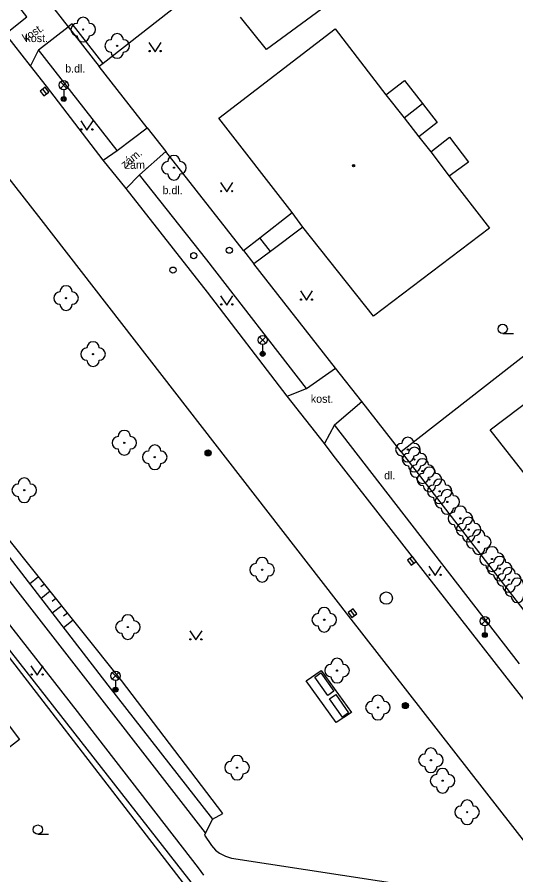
# Model space of a CAD drawing. Extents: x -600391 to -599491, y -1160176 to -1159402.
# Drawn here: x -600285.6 to -600245.1, y -1160073.3 to -1160003.6 of the extents above; entities that cross this region are included whole.
import ezdxf

# ---------------------------------------------------------------- set-up
doc = ezdxf.new("R2010")
doc.units = 0
for name, color, linetype in [('Level 10', 7, 'Continuous'), ('Level 11', 7, 'Continuous'), ('Level 14', 7, 'Continuous'), ('Level 15', 7, 'Continuous'), ('Level 22', 7, 'Continuous'), ('Level 25', 7, 'Continuous'), ('Level 27', 7, 'Continuous'), ('Level 28', 7, 'Continuous'), ('Level 33', 7, 'Continuous'), ('Level 36', 7, 'Continuous'), ('Level 39', 7, 'Continuous'), ('Level 40', 7, 'Continuous'), ('Level 5', 7, 'Continuous'), ('Level 51', 7, 'Continuous'), ('Level 7', 7, 'Continuous'), ('Level 8', 7, 'Continuous')]:
    doc.layers.add(name, color=color, linetype=linetype)

msp = doc.modelspace()

# ---------------------------------------------------------------- linework, layer by layer
at = {"layer": 'Level 10'}
for points in [[(-600310.39, -1159986), (-600301.49, -1159997.27), (-600283.69, -1160020.07), (-600258.7, -1160052.27), (-600242.9, -1160072.54)], [(-600284.52, -1160007.58), (-600286.55, -1160004.99)], [(-600278.63, -1160015.26), (-600283.23, -1160009.23), (-600284.52, -1160007.58)], [(-600276.76, -1160017.55), (-600278.63, -1160015.26)], [(-600263.67, -1160034.4), (-600270.16, -1160025.97), (-600276.76, -1160017.55)], [(-600260.66, -1160038.27), (-600263.67, -1160034.4)], [(-600223.8, -1160083.35), (-600225.26, -1160082.99), (-600226.39, -1160082.24), (-600243.5, -1160060.28), (-600246.01, -1160057.06), (-600259.94, -1160039.2), (-600260.66, -1160038.27)]]:
    msp.add_lwpolyline(points, dxfattribs=at)
at = {"layer": 'Level 11'}
for points in [[(-600286.55, -1160004.99), (-600284.82, -1160003.6), (-600288.16, -1159999.31), (-600289.9, -1160000.71)], [(-600283.87, -1160006.28), (-600281.45, -1160004.43)], [(-600283.87, -1160006.28), (-600284.52, -1160007.58)], [(-600277.48, -1160014.47), (-600283.87, -1160006.28)], [(-600255.66, -1160009.94), (-600254.16, -1160008.77), (-600252.69, -1160010.66)], [(-600254.18, -1160011.82), (-600252.69, -1160010.66)], [(-600252.69, -1160010.66), (-600251.49, -1160012.2), (-600252.98, -1160013.36)], [(-600277.48, -1160014.47), (-600275.04, -1160012.62)], [(-600252.02, -1160014.58), (-600250.5, -1160013.37), (-600248.97, -1160015.41), (-600250.54, -1160016.56)], [(-600278.63, -1160015.26), (-600277.48, -1160014.47)], [(-600275.67, -1160016.43), (-600273.53, -1160014.55)], [(-600275.67, -1160016.43), (-600276.76, -1160017.55)], [(-600262.12, -1160033.8), (-600270.19, -1160023.35), (-600275.67, -1160016.43)], [(-600270.31, -1160069.87), (-600277.95, -1160060.05), (-600309.2, -1160019.89), (-600308.6, -1160019.4)], [(-600308.67, -1160019.36), (-600308.6, -1160019.4), (-600307.74, -1160019.96), (-600297.07, -1160033.59), (-600287.02, -1160046.53), (-600278.23, -1160057.89), (-600269.75, -1160068.77)], [(-600265.9, -1160021.55), (-600263.28, -1160019.49)], [(-600262.41, -1160020.69), (-600265.02, -1160022.66)], [(-600267.23, -1160022.59), (-600265.9, -1160021.55)], [(-600265.02, -1160022.66), (-600265.9, -1160021.55)], [(-600265.02, -1160022.66), (-600266.38, -1160023.68)], [(-600262.12, -1160033.8), (-600259.75, -1160032.14)], [(-600263.67, -1160034.4), (-600262.12, -1160033.8)], [(-600259.84, -1160036.73), (-600257.62, -1160034.85)], [(-600259.84, -1160036.73), (-600260.66, -1160038.27)], [(-600244.82, -1160056.16), (-600259.84, -1160036.73)], [(-600270.44, -1160073.3), (-600270.89, -1160072.72), (-600279.69, -1160061.33), (-600280.7, -1160060.03), (-600290, -1160048.14)], [(-600294.89, -1160049.78), (-600285.4, -1160062.29), (-600294.15, -1160069.09)], [(-600262.15, -1160057.54), (-600260.91, -1160056.7)], [(-600260.91, -1160056.7), (-600258.47, -1160060.1), (-600259.71, -1160060.92), (-600262.15, -1160057.54)], [(-600261.43, -1160057.23), (-600260.94, -1160056.88), (-600259.89, -1160058.37), (-600260.38, -1160058.71), (-600261.43, -1160057.23)], [(-600260.23, -1160059), (-600259.74, -1160058.65), (-600258.69, -1160060.14), (-600259.18, -1160060.48), (-600260.23, -1160059)], [(-600269.75, -1160068.77), (-600270.31, -1160069.87), (-600270.4, -1160070.05), (-600269.83, -1160070.91)], [(-600269.83, -1160070.91), (-600269.5, -1160071.27), (-600269.17, -1160071.52), (-600269.11, -1160071.56), (-600268.68, -1160071.78), (-600268.21, -1160071.92)], [(-600268.21, -1160071.92), (-600253.19, -1160074.23), (-600244.65, -1160075.54), (-600243.72, -1160075.27)]]:
    msp.add_lwpolyline(points, dxfattribs=at)
at = {"layer": 'Level 14'}
msp.add_lwpolyline([(-600269.75, -1160068.77), (-600268.89, -1160068.29), (-600277.13, -1160057.5), (-600286.89, -1160045.28), (-600296.8, -1160033.43), (-600307.92, -1160019.03), (-600308.6, -1160019.4)], dxfattribs=at)
at = {"layer": 'Level 15'}
for points in [[(-600283.86, -1160049.08), (-600284.59, -1160049.67)], [(-600283.39, -1160049.67), (-600283.69, -1160049.91)], [(-600282.92, -1160050.25), (-600283.67, -1160050.86)], [(-600282.45, -1160050.84), (-600282.76, -1160051.08)], [(-600281.98, -1160051.43), (-600282.76, -1160052.04)], [(-600281.83, -1160052.26), (-600281.52, -1160052.01)], [(-600281.05, -1160052.6), (-600281.84, -1160053.23)]]:
    msp.add_lwpolyline(points, dxfattribs=at)
at = {"layer": 'Level 22'}
for centre in [(-600280.24, -1160004.64), (-600277.48, -1160005.97), (-600272.87, -1160015.86), (-600281.63, -1160026.45), (-600279.44, -1160031), (-600276.9, -1160038.2), (-600253.88, -1160038.75), (-600274.43, -1160039.37), (-600253.34, -1160039.56), (-600252.7, -1160040.5), (-600252.13, -1160041.18), (-600285.02, -1160042.05), (-600251.3, -1160042.14), (-600250.68, -1160043), (-600249.62, -1160044.34), (-600248.95, -1160045.25), (-600248.13, -1160046.26), (-600247.05, -1160047.64), (-600265.71, -1160048.51), (-600246.42, -1160048.42), (-600245.67, -1160049.33), (-600260.67, -1160052.57), (-600276.61, -1160053.16), (-600259.63, -1160056.7), (-600256.31, -1160059.7), (-600252.01, -1160063.98), (-600267.75, -1160064.58), (-600251.06, -1160065.64), (-600249.07, -1160068.2)]:
    msp.add_circle(centre, 0.05, dxfattribs=at)
for centre, start, end in [((-600280.24, -1160004.14), 0, 180), ((-600280.74, -1160004.64), 90, 270), ((-600279.74, -1160004.64), 270, 90), ((-600280.24, -1160005.14), 180, 0), ((-600277.48, -1160005.47), 0, 180), ((-600277.98, -1160005.97), 90, 270), ((-600276.98, -1160005.97), 270, 90), ((-600277.48, -1160006.47), 180, 0), ((-600272.87, -1160015.36), 0, 180), ((-600273.37, -1160015.86), 90, 270), ((-600272.37, -1160015.86), 270, 90), ((-600272.87, -1160016.36), 180, 0), ((-600281.63, -1160025.95), 0, 180), ((-600282.13, -1160026.45), 90, 270), ((-600281.13, -1160026.45), 270, 90), ((-600281.63, -1160026.95), 180, 0), ((-600279.94, -1160031), 90, 270), ((-600279.44, -1160030.5), 0, 180), ((-600278.94, -1160031), 270, 90), ((-600279.44, -1160031.5), 180, 0), ((-600276.9, -1160037.7), 0, 180), ((-600277.4, -1160038.2), 90, 270), ((-600276.4, -1160038.2), 270, 90), ((-600253.88, -1160038.25), 0, 180), ((-600276.9, -1160038.7), 180, 0), ((-600274.43, -1160038.87), 0, 180), ((-600254.38, -1160038.75), 90, 270), ((-600253.34, -1160039.06), 0, 180), ((-600253.38, -1160038.75), 270, 90), ((-600274.93, -1160039.37), 90, 270), ((-600273.93, -1160039.37), 270, 90), ((-600253.88, -1160039.25), 180, 0), ((-600253.84, -1160039.56), 90, 270), ((-600252.7, -1160040), 0, 180), ((-600252.84, -1160039.56), 270, 90), ((-600274.43, -1160039.87), 180, 0), ((-600253.34, -1160040.06), 180, 0), ((-600253.2, -1160040.5), 90, 270), ((-600252.13, -1160040.68), 0, 180), ((-600252.2, -1160040.5), 270, 90), ((-600252.63, -1160041.18), 90, 270), ((-600251.63, -1160041.18), 270, 90), ((-600285.52, -1160042.05), 90, 270), ((-600285.02, -1160041.55), 0, 180), ((-600284.52, -1160042.05), 270, 90), ((-600252.7, -1160041), 180, 0), ((-600251.8, -1160042.14), 90, 270), ((-600251.3, -1160041.64), 0, 180), ((-600250.8, -1160042.14), 270, 90), ((-600252.13, -1160041.68), 180, 0), ((-600250.68, -1160042.5), 0, 180), ((-600285.02, -1160042.55), 180, 0), ((-600251.3, -1160042.64), 180, 0), ((-600251.18, -1160043), 90, 270), ((-600250.18, -1160043), 270, 90), ((-600250.68, -1160043.5), 180, 0), ((-600249.62, -1160043.84), 0, 180), ((-600250.12, -1160044.34), 90, 270), ((-600248.95, -1160044.75), 0, 180), ((-600249.12, -1160044.34), 270, 90), ((-600249.62, -1160044.84), 180, 0), ((-600249.45, -1160045.25), 90, 270), ((-600248.45, -1160045.25), 270, 90), ((-600248.95, -1160045.75), 180, 0), ((-600248.63, -1160046.26), 90, 270), ((-600248.13, -1160045.76), 0, 180), ((-600247.63, -1160046.26), 270, 90), ((-600248.13, -1160046.76), 180, 0), ((-600247.55, -1160047.64), 90, 270), ((-600247.05, -1160047.14), 0, 180), ((-600246.55, -1160047.64), 270, 90), ((-600265.71, -1160048.01), 0, 180), ((-600246.42, -1160047.92), 0, 180), ((-600266.21, -1160048.51), 90, 270), ((-600265.21, -1160048.51), 270, 90), ((-600247.05, -1160048.14), 180, 0), ((-600246.92, -1160048.42), 90, 270), ((-600245.67, -1160048.83), 0, 180), ((-600245.92, -1160048.42), 270, 90), ((-600265.71, -1160049.01), 180, 0), ((-600246.42, -1160048.92), 180, 0), ((-600246.17, -1160049.33), 90, 270), ((-600244.99, -1160049.68), 0, 180), ((-600245.17, -1160049.33), 270, 90), ((-600245.67, -1160049.83), 180, 0), ((-600245.49, -1160050.18), 90, 270), ((-600244.99, -1160050.68), 180, 0), ((-600261.17, -1160052.57), 90, 270), ((-600260.67, -1160052.07), 0, 180), ((-600260.17, -1160052.57), 270, 90), ((-600277.11, -1160053.16), 90, 270), ((-600276.61, -1160052.66), 0, 180), ((-600276.11, -1160053.16), 270, 90), ((-600260.67, -1160053.07), 180, 0), ((-600276.61, -1160053.66), 180, 0), ((-600260.13, -1160056.7), 90, 270), ((-600259.63, -1160056.2), 0, 180), ((-600259.13, -1160056.7), 270, 90), ((-600259.63, -1160057.2), 180, 0), ((-600256.31, -1160059.2), 0, 180), ((-600256.81, -1160059.7), 90, 270), ((-600255.81, -1160059.7), 270, 90), ((-600256.31, -1160060.2), 180, 0), ((-600252.01, -1160063.48), 0, 180), ((-600267.75, -1160064.08), 0, 180), ((-600252.51, -1160063.98), 90, 270), ((-600251.51, -1160063.98), 270, 90), ((-600268.25, -1160064.58), 90, 270), ((-600267.25, -1160064.58), 270, 90), ((-600252.01, -1160064.48), 180, 0), ((-600267.75, -1160065.08), 180, 0), ((-600251.56, -1160065.64), 90, 270), ((-600251.06, -1160065.14), 0, 180), ((-600250.56, -1160065.64), 270, 90), ((-600251.06, -1160066.14), 180, 0), ((-600249.07, -1160067.7), 0, 180), ((-600249.57, -1160068.2), 90, 270), ((-600248.57, -1160068.2), 270, 90), ((-600249.07, -1160068.7), 180, 0)]:
    msp.add_arc(centre, 0.5, start, end, dxfattribs=at)
at = {"layer": 'Level 25'}
for centre, radius in [((-600270.1, -1160039.02), 0.25), ((-600270.1, -1160039.02), 0.2), ((-600270.1, -1160039.02), 0.15), ((-600270.1, -1160039.02), 0.1), ((-600270.1, -1160039.02), 0.05), ((-600254.08, -1160059.54), 0.25), ((-600254.08, -1160059.54), 0.2), ((-600254.08, -1160059.54), 0.15), ((-600254.08, -1160059.54), 0.1), ((-600254.08, -1160059.54), 0.05)]:
    msp.add_circle(centre, radius, dxfattribs=at)
at = {"layer": 'Level 27'}
for p, q in [((-600283.532, -1160009.481), (-600283.228, -1160009.879)), ((-600253.712, -1160047.591), (-600253.408, -1160047.989)), ((-600258.532, -1160051.831), (-600258.228, -1160052.229))]:
    msp.add_line(p, q, dxfattribs=at)
for points in [[(-600283.73, -1160009.633), (-600283.427, -1160010.03), (-600283.03, -1160009.727), (-600283.333, -1160009.33)], [(-600253.91, -1160047.743), (-600253.607, -1160048.14), (-600253.21, -1160047.837), (-600253.513, -1160047.44)], [(-600258.73, -1160051.983), (-600258.427, -1160052.38), (-600258.03, -1160052.077), (-600258.333, -1160051.68)]]:
    msp.add_lwpolyline(points, close=True, dxfattribs=at)
msp.add_circle((-600255.63, -1160050.81), 0.5, dxfattribs=at)
at = {"layer": 'Level 28'}
for centre in [(-600271.26, -1160023), (-600268.37, -1160022.56), (-600272.95, -1160024.18)]:
    msp.add_circle(centre, 0.25, dxfattribs=at)
at = {"layer": 'Level 33'}
for p, q in [((-600282.085, -1160009.42), (-600281.555, -1160008.89)), ((-600282.085, -1160008.89), (-600281.555, -1160009.42)), ((-600281.82, -1160009.53), (-600281.82, -1160010.28)), ((-600265.935, -1160030.12), (-600265.405, -1160029.59)), ((-600265.935, -1160029.59), (-600265.405, -1160030.12)), ((-600265.67, -1160030.23), (-600265.67, -1160030.98)), ((-600247.895, -1160052.95), (-600247.365, -1160052.42)), ((-600247.895, -1160052.42), (-600247.365, -1160052.95)), ((-600247.63, -1160053.06), (-600247.63, -1160053.81)), ((-600277.875, -1160057.39), (-600277.345, -1160056.86)), ((-600277.875, -1160056.86), (-600277.345, -1160057.39)), ((-600277.61, -1160057.5), (-600277.61, -1160058.25))]:
    msp.add_line(p, q, dxfattribs=at)
for centre, radius in [((-600281.82, -1160009.155), 0.375), ((-600281.82, -1160010.28), 0.2), ((-600281.82, -1160010.28), 0.145), ((-600281.82, -1160010.28), 0.0876), ((-600265.67, -1160029.855), 0.375), ((-600265.67, -1160030.98), 0.2), ((-600265.67, -1160030.98), 0.145), ((-600265.67, -1160030.98), 0.0876), ((-600247.63, -1160052.685), 0.375), ((-600247.63, -1160053.81), 0.2), ((-600247.63, -1160053.81), 0.145), ((-600247.63, -1160053.81), 0.0876), ((-600277.61, -1160057.125), 0.375), ((-600277.61, -1160058.25), 0.2), ((-600277.61, -1160058.25), 0.145), ((-600277.61, -1160058.25), 0.0876)]:
    msp.add_circle(centre, radius, dxfattribs=at)
at = {"layer": 'Level 36'}
for p, q in [((-600246.18, -1160029.325), (-600245.305, -1160029.325)), ((-600283.92, -1160069.985), (-600283.045, -1160069.985))]:
    msp.add_line(p, q, dxfattribs=at)
for points in [[(-600274.9, -1160005.69), (-600274.4, -1160006.44), (-600273.9, -1160005.69)], [(-600280.44, -1160012.05), (-600279.94, -1160012.8), (-600279.44, -1160012.05)], [(-600269.09, -1160017.07), (-600268.59, -1160017.82), (-600268.09, -1160017.07)], [(-600269.08, -1160026.26), (-600268.58, -1160027.01), (-600268.08, -1160026.26)], [(-600262.61, -1160025.87), (-600262.11, -1160026.62), (-600261.61, -1160025.87)], [(-600252.17, -1160048.22), (-600251.67, -1160048.97), (-600251.17, -1160048.22)], [(-600271.59, -1160053.46), (-600271.09, -1160054.21), (-600270.59, -1160053.46)], [(-600284.48, -1160056.32), (-600283.98, -1160057.07), (-600283.48, -1160056.32)]]:
    msp.add_lwpolyline(points, dxfattribs=at)
for centre, radius in [((-600274.85, -1160006.39), 0.05), ((-600273.951, -1160006.39), 0.05), ((-600280.39, -1160012.75), 0.05), ((-600279.491, -1160012.75), 0.05), ((-600269.04, -1160017.77), 0.05), ((-600268.141, -1160017.77), 0.05), ((-600269.03, -1160026.96), 0.05), ((-600268.131, -1160026.96), 0.05), ((-600262.56, -1160026.57), 0.05), ((-600261.661, -1160026.57), 0.05), ((-600246.18, -1160028.95), 0.375), ((-600252.12, -1160048.92), 0.05), ((-600251.221, -1160048.92), 0.05), ((-600271.54, -1160054.16), 0.05), ((-600270.641, -1160054.16), 0.05), ((-600284.43, -1160057.02), 0.05), ((-600283.531, -1160057.02), 0.05), ((-600283.92, -1160069.61), 0.375)]:
    msp.add_circle(centre, radius, dxfattribs=at)
at = {"layer": 'Level 39'}
for radius in [0.09, 0.0398]:
    msp.add_circle((-600258.29, -1160015.69), radius, dxfattribs=at)
at = {"layer": 'Level 5'}
for points in [[(-600260.48, -1160002.7), (-600265.37, -1160006.26)], [(-600265.37, -1160006.26), (-600267.48, -1160003.63)], [(-600269.24, -1160011.85), (-600259.79, -1160004.57)], [(-600259.79, -1160004.57), (-600255.66, -1160009.94)], [(-600255.66, -1160009.94), (-600254.18, -1160011.82)], [(-600263.28, -1160019.49), (-600269.24, -1160011.85)], [(-600254.18, -1160011.82), (-600252.98, -1160013.36)], [(-600252.98, -1160013.36), (-600252.02, -1160014.58)], [(-600252.02, -1160014.58), (-600250.54, -1160016.56)], [(-600250.54, -1160016.56), (-600247.25, -1160020.76)], [(-600262.41, -1160020.69), (-600263.28, -1160019.49)], [(-600256.66, -1160027.92), (-600262.41, -1160020.69)], [(-600247.25, -1160020.76), (-600256.66, -1160027.92)]]:
    msp.add_lwpolyline(points, dxfattribs=at)
at = {"layer": 'Level 51'}
for points in [[(-600247.19, -1160037.16), (-600242.43, -1160033.56)], [(-600242.98, -1160042.53), (-600247.19, -1160037.16)]]:
    msp.add_lwpolyline(points, dxfattribs=at)
at = {"layer": 'Level 7'}
for points in [[(-600261.22, -1159993.64), (-600264.36, -1159996.22), (-600278.63, -1160007.39)], [(-600278.63, -1160007.39), (-600281.14, -1160004.18), (-600281.45, -1160004.43)], [(-600281.45, -1160004.43), (-600278.94, -1160007.65)], [(-600278.63, -1160007.39), (-600278.94, -1160007.65)], [(-600275.04, -1160012.62), (-600278.94, -1160007.65)], [(-600267.23, -1160022.59), (-600273.53, -1160014.55)], [(-600259.75, -1160032.14), (-600266.38, -1160023.68)], [(-600241.14, -1160028.57), (-600254.43, -1160038.93)], [(-600257.62, -1160034.85), (-600259.75, -1160032.14)], [(-600254.43, -1160038.93), (-600257.62, -1160034.85)], [(-600254.43, -1160038.93), (-600242.43, -1160054.45)], [(-600291.19, -1160048.68), (-600291.46, -1160048.9), (-600271.66, -1160074.55), (-600280.55, -1160083.87), (-600298.1, -1160072.26)], [(-600280.58, -1160084.57), (-600270.98, -1160074.51), (-600291, -1160048.92)]]:
    msp.add_lwpolyline(points, dxfattribs=at)
at = {"layer": 'Level 8'}
for points in [[(-600283.12, -1160002.31), (-600281.45, -1160004.43)], [(-600275.04, -1160012.62), (-600273.53, -1160014.55)], [(-600267.23, -1160022.59), (-600266.38, -1160023.68)]]:
    msp.add_lwpolyline(points, dxfattribs=at)

# ---------------------------------------------------------------- texts
at = {"layer": 'Level 40'}
for s, rotation, p in [('kost.', 32.48, (-600284.93, -1160005.66)), ('zám.', 38.49, (-600276.87, -1160015.95))]:
    msp.add_text(s, height=0.65, rotation=rotation, dxfattribs=at).set_placement(p)
for s, p in [('kost.', (-600284.93, -1160005.66)), ('b.dl.', (-600281.7, -1160008.13)), ('b.dl.', (-600281.7, -1160008.13)), ('zám.', (-600276.87, -1160015.95)), ('b.dl.', (-600273.8, -1160018.01)), ('b.dl.', (-600273.8, -1160018.01)), ('kost.', (-600261.76, -1160034.95)), ('kost.', (-600261.76, -1160034.95)), ('dl.', (-600255.81, -1160041.17)), ('dl.', (-600255.81, -1160041.17))]:
    msp.add_text(s, height=0.65, dxfattribs=at).set_placement(p)

doc.saveas('drawing.dxf')
